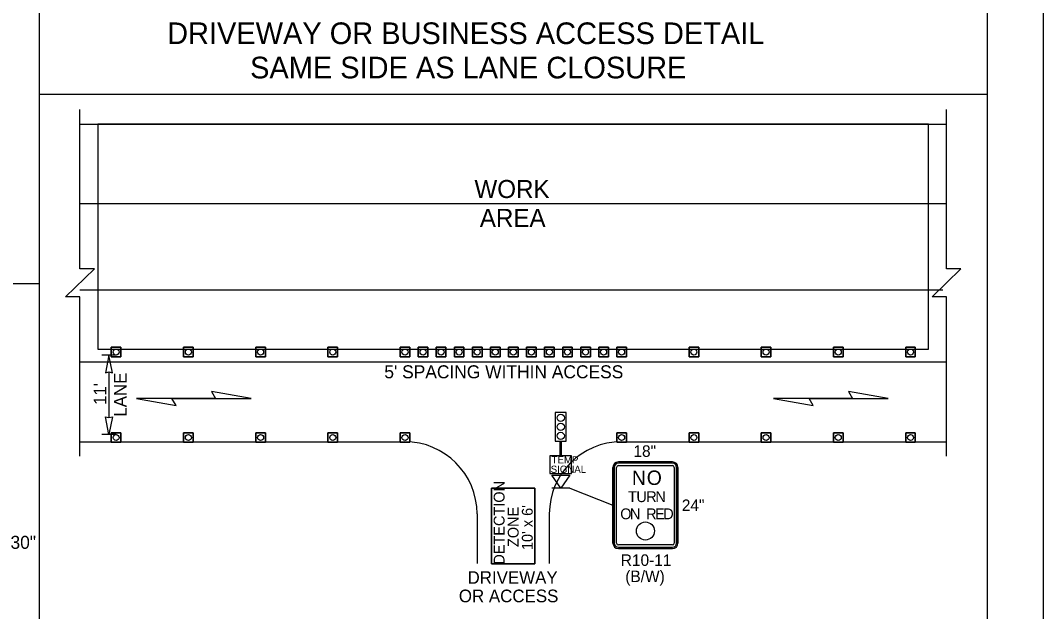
# Model space of a CAD drawing. Extents: x 99979.8 to 100075.7, y 99995 to 100010.7.
# Drawn here: x 100050.4 to 100056.06, y 100004.3 to 100007.58 of the extents above; entities that cross this region are included whole.
import ezdxf

# ---------------------------------------------------------------- set-up
doc = ezdxf.new("R2010")
doc.units = 0
for name, color, linetype in [('Default', 7, 'Continuous'), ('RD_ED_DrivewayEdge', 7, 'Continuous'), ('RD_ED_ShoulderPavedEdge', 7, 'Continuous'), ('RD_MK_LineEdgeWhite', 7, 'Continuous'), ('RD_MK_LineSkipCenter', 7, 'Continuous'), ('SH_DE_DetailHeading2Text', 7, 'Continuous'), ('SH_GI_PlotLimits', 7, 'Continuous'), ('SH_GI_SheetBorder', 7, 'Continuous'), ('TR_SN_ConstructionSigns', 7, 'Continuous'), ('TR_WZ_PortableSignMountBlk-Wht', 7, 'Continuous'), ('TR_WZ_TempSignal', 7, 'Continuous'), ('TR_WZ_TrafficCone', 7, 'Continuous'), ('TR_WZ_WorkAreaLabel', 7, 'Continuous'), ('TR_WZ_WorkZoneDetails', 7, 'Continuous'), ('TR_WZ_WorkZoneTextCurrent', 7, 'Continuous')]:
    doc.layers.add(name, color=color, linetype=linetype)

msp = doc.modelspace()

# ---------------------------------------------------------------- linework, layer by layer
at = {"layer": 'Default'}
msp.add_circle((100053.8574, 100004.7505), 0.05, dxfattribs=at)
at = {"layer": 'RD_ED_DrivewayEdge'}
for p, q in [((100052.925, 100004.845), (100052.925, 100004.5696)), ((100053.325, 100004.845), (100053.325, 100004.5696))]:
    msp.add_line(p, q, dxfattribs=at)
for centre, start, end in [((100052.525, 100004.845), 0, 90), ((100053.725, 100004.845), 90, 180)]:
    msp.add_arc(centre, 0.4, start, end, dxfattribs=at)
at = {"layer": 'RD_ED_ShoulderPavedEdge'}
for p, q in [((100050.725, 100007.005), (100055.525, 100007.005)), ((100050.725, 100005.245), (100052.525, 100005.245)), ((100050.725, 100005.245), (100052.525, 100005.245)), ((100053.725, 100005.245), (100055.525, 100005.245)), ((100053.725, 100005.245), (100055.525, 100005.245))]:
    msp.add_line(p, q, dxfattribs=at)
at = {"layer": 'RD_MK_LineEdgeWhite'}
for p, q in [((100050.725, 100006.565), (100055.525, 100006.565)), ((100055.525, 100005.685), (100050.725, 100005.685))]:
    msp.add_line(p, q, dxfattribs=at)
at = {"layer": 'RD_MK_LineSkipCenter'}
msp.add_lwpolyline([(100055.5043, 100006.085), (100050.725, 100006.085)], dxfattribs=at)
at = {"layer": 'SH_GI_PlotLimits'}
msp.add_lwpolyline([(100039.0625, 99999.6875), (100056.0625, 99999.6875), (100056.0625, 100010.6875), (100039.0625, 100010.6875)], close=True, dxfattribs=at)
at = {"layer": 'SH_GI_SheetBorder'}
msp.add_line((100055.75, 100010.375), (100055.75, 100000), dxfattribs=at)
at = {"layer": 'TR_SN_ConstructionSigns'}
for p, q in [((100053.7074, 100005.133), (100054.0074, 100005.133)), ((100054.0074, 100005.133), (100053.7074, 100005.133)), ((100054.0074, 100005.133), (100053.7074, 100005.133)), ((100054.0074, 100005.1255), (100053.7074, 100005.1255)), ((100053.6774, 100004.683), (100053.6774, 100005.103)), ((100053.6774, 100005.103), (100053.6774, 100004.683)), ((100053.6774, 100005.103), (100053.6774, 100004.683)), ((100053.6849, 100005.103), (100053.6849, 100004.683)), ((100053.6974, 100004.683), (100053.6974, 100005.103)), ((100053.7074, 100005.113), (100054.0074, 100005.113)), ((100054.0174, 100005.103), (100054.0174, 100004.683)), ((100054.0299, 100004.683), (100054.0299, 100005.103)), ((100054.0374, 100005.103), (100054.0374, 100004.683)), ((100054.0374, 100004.683), (100054.0374, 100005.103)), ((100054.0374, 100004.683), (100054.0374, 100005.103)), ((100054.0074, 100004.673), (100053.7074, 100004.673)), ((100053.7074, 100004.6605), (100054.0074, 100004.6605)), ((100054.0074, 100004.653), (100053.7074, 100004.653)), ((100053.7074, 100004.653), (100054.0074, 100004.653)), ((100053.7074, 100004.653), (100054.0074, 100004.653))]:
    msp.add_line(p, q, dxfattribs=at)
for centre, radius, start, end in [((100053.7074, 100005.103), 0.03, 90, 180), ((100053.7074, 100005.103), 0.03, 90, 180), ((100053.7074, 100005.103), 0.03, 90, 180), ((100053.7074, 100005.103), 0.0225, 90, 180), ((100054.0074, 100005.103), 0.03, 0, 90), ((100054.0074, 100005.103), 0.03, 0, 90), ((100054.0074, 100005.103), 0.03, 0, 90), ((100054.0074, 100005.103), 0.0225, 0, 90), ((100053.7074, 100005.103), 0.01, 90, 180), ((100054.0074, 100005.103), 0.01, 0, 90), ((100053.7074, 100004.683), 0.03, 180, 270), ((100053.7074, 100004.683), 0.03, 180, 270), ((100053.7074, 100004.683), 0.03, 180, 270), ((100053.7074, 100004.683), 0.0225, 180, 270), ((100053.7074, 100004.683), 0.01, 180, 270), ((100054.0074, 100004.683), 0.03, 270, 0), ((100054.0074, 100004.683), 0.03, 270, 0), ((100054.0074, 100004.683), 0.0225, 270, 0), ((100054.0074, 100004.683), 0.01, 270, 0), ((100054.0074, 100004.683), 0.03, 270, 0)]:
    msp.add_arc(centre, radius, start, end, dxfattribs=at)
at = {"layer": 'TR_WZ_PortableSignMountBlk-Wht'}
msp.add_line((100053.4383, 100004.9878), (100053.3383, 100004.9878), dxfattribs=at)
msp.add_lwpolyline([(100053.3884, 100004.9878), (100053.3383, 100005.0596), (100053.4383, 100005.0596)], close=True, dxfattribs=at)
at = {"layer": 'TR_WZ_TempSignal'}
for p, q in [((100053.4182, 100005.4071), (100053.3583, 100005.4071)), ((100053.3583, 100005.4071), (100053.3583, 100005.2474)), ((100053.4182, 100005.2474), (100053.4182, 100005.4071)), ((100053.3583, 100005.2474), (100053.4182, 100005.2474)), ((100053.4483, 100005.1674), (100053.3283, 100005.1674)), ((100053.3283, 100005.1674), (100053.3283, 100005.1229)), ((100053.3283, 100005.1229), (100053.3283, 100005.1141)), ((100053.4483, 100005.0696), (100053.4483, 100005.1674)), ((100053.3283, 100005.1141), (100053.3283, 100005.0696)), ((100053.3283, 100005.0696), (100053.4483, 100005.0696))]:
    msp.add_line(p, q, dxfattribs=at)
for points in [[(100053.4182, 100005.4071), (100053.3583, 100005.4071), (100053.3583, 100005.2474), (100053.4182, 100005.2474), (100053.4182, 100005.4071)], [(100053.4483, 100005.1674), (100053.3283, 100005.1674), (100053.3283, 100005.0696), (100053.4483, 100005.0696), (100053.4483, 100005.1674)]]:
    msp.add_lwpolyline(points, dxfattribs=at)
msp.add_lwpolyline([(100053.3858, 100005.2474), (100053.3908, 100005.2474), (100053.3908, 100005.1674), (100053.3858, 100005.1674)], close=True, dxfattribs=at)
for centre in [(100053.3883, 100005.3772), (100053.3883, 100005.3772), (100053.3883, 100005.3273), (100053.3883, 100005.3273), (100053.3883, 100005.2773), (100053.3883, 100005.2773)]:
    msp.add_circle(centre, 0.02, dxfattribs=at)
at = {"layer": 'TR_WZ_TrafficCone'}
for points in [[(100050.899, 100005.7683), (100050.9523, 100005.7683), (100050.9523, 100005.715), (100050.899, 100005.715), (100050.899, 100005.7683)], [(100050.899, 100005.715), (100050.9523, 100005.715), (100050.9523, 100005.7683), (100050.899, 100005.7683), (100050.899, 100005.715)], [(100051.299, 100005.7683), (100051.3523, 100005.7683), (100051.3523, 100005.715), (100051.299, 100005.715), (100051.299, 100005.7683)], [(100051.299, 100005.715), (100051.3523, 100005.715), (100051.3523, 100005.7683), (100051.299, 100005.7683), (100051.299, 100005.715)], [(100051.699, 100005.7683), (100051.7523, 100005.7683), (100051.7523, 100005.715), (100051.699, 100005.715), (100051.699, 100005.7683)], [(100051.699, 100005.715), (100051.7523, 100005.715), (100051.7523, 100005.7683), (100051.699, 100005.7683), (100051.699, 100005.715)], [(100052.099, 100005.7683), (100052.1523, 100005.7683), (100052.1523, 100005.715), (100052.099, 100005.715), (100052.099, 100005.7683)], [(100052.099, 100005.715), (100052.1523, 100005.715), (100052.1523, 100005.7683), (100052.099, 100005.7683), (100052.099, 100005.715)], [(100052.499, 100005.7683), (100052.5523, 100005.7683), (100052.5523, 100005.715), (100052.499, 100005.715), (100052.499, 100005.7683)], [(100052.499, 100005.715), (100052.5523, 100005.715), (100052.5523, 100005.7683), (100052.499, 100005.7683), (100052.499, 100005.715)], [(100052.599, 100005.7683), (100052.6523, 100005.7683), (100052.6523, 100005.715), (100052.599, 100005.715), (100052.599, 100005.7683)], [(100052.599, 100005.715), (100052.6523, 100005.715), (100052.6523, 100005.7683), (100052.599, 100005.7683), (100052.599, 100005.715)], [(100052.699, 100005.7683), (100052.7523, 100005.7683), (100052.7523, 100005.715), (100052.699, 100005.715), (100052.699, 100005.7683)], [(100052.699, 100005.715), (100052.7523, 100005.715), (100052.7523, 100005.7683), (100052.699, 100005.7683), (100052.699, 100005.715)], [(100052.799, 100005.7683), (100052.8523, 100005.7683), (100052.8523, 100005.715), (100052.799, 100005.715), (100052.799, 100005.7683)], [(100052.799, 100005.715), (100052.8523, 100005.715), (100052.8523, 100005.7683), (100052.799, 100005.7683), (100052.799, 100005.715)], [(100052.899, 100005.7683), (100052.9523, 100005.7683), (100052.9523, 100005.715), (100052.899, 100005.715), (100052.899, 100005.7683)], [(100052.899, 100005.715), (100052.9523, 100005.715), (100052.9523, 100005.7683), (100052.899, 100005.7683), (100052.899, 100005.715)], [(100052.999, 100005.7683), (100053.0523, 100005.7683), (100053.0523, 100005.715), (100052.999, 100005.715), (100052.999, 100005.7683)], [(100052.999, 100005.715), (100053.0523, 100005.715), (100053.0523, 100005.7683), (100052.999, 100005.7683), (100052.999, 100005.715)], [(100053.099, 100005.7683), (100053.1523, 100005.7683), (100053.1523, 100005.715), (100053.099, 100005.715), (100053.099, 100005.7683)], [(100053.099, 100005.715), (100053.1523, 100005.715), (100053.1523, 100005.7683), (100053.099, 100005.7683), (100053.099, 100005.715)], [(100053.199, 100005.7683), (100053.2523, 100005.7683), (100053.2523, 100005.715), (100053.199, 100005.715), (100053.199, 100005.7683)], [(100053.199, 100005.715), (100053.2523, 100005.715), (100053.2523, 100005.7683), (100053.199, 100005.7683), (100053.199, 100005.715)], [(100053.299, 100005.7683), (100053.3523, 100005.7683), (100053.3523, 100005.715), (100053.299, 100005.715), (100053.299, 100005.7683)], [(100053.299, 100005.715), (100053.3523, 100005.715), (100053.3523, 100005.7683), (100053.299, 100005.7683), (100053.299, 100005.715)], [(100053.399, 100005.7683), (100053.4523, 100005.7683), (100053.4523, 100005.715), (100053.399, 100005.715), (100053.399, 100005.7683)], [(100053.399, 100005.715), (100053.4523, 100005.715), (100053.4523, 100005.7683), (100053.399, 100005.7683), (100053.399, 100005.715)], [(100053.499, 100005.7683), (100053.5523, 100005.7683), (100053.5523, 100005.715), (100053.499, 100005.715), (100053.499, 100005.7683)], [(100053.499, 100005.715), (100053.5523, 100005.715), (100053.5523, 100005.7683), (100053.499, 100005.7683), (100053.499, 100005.715)], [(100053.599, 100005.7683), (100053.6523, 100005.7683), (100053.6523, 100005.715), (100053.599, 100005.715), (100053.599, 100005.7683)], [(100053.599, 100005.715), (100053.6523, 100005.715), (100053.6523, 100005.7683), (100053.599, 100005.7683), (100053.599, 100005.715)], [(100053.699, 100005.7683), (100053.7523, 100005.7683), (100053.7523, 100005.715), (100053.699, 100005.715), (100053.699, 100005.7683)], [(100053.699, 100005.715), (100053.7523, 100005.715), (100053.7523, 100005.7683), (100053.699, 100005.7683), (100053.699, 100005.715)], [(100054.099, 100005.7683), (100054.1523, 100005.7683), (100054.1523, 100005.715), (100054.099, 100005.715), (100054.099, 100005.7683)], [(100054.099, 100005.715), (100054.1523, 100005.715), (100054.1523, 100005.7683), (100054.099, 100005.7683), (100054.099, 100005.715)], [(100054.499, 100005.7683), (100054.5523, 100005.7683), (100054.5523, 100005.715), (100054.499, 100005.715), (100054.499, 100005.7683)], [(100054.499, 100005.715), (100054.5523, 100005.715), (100054.5523, 100005.7683), (100054.499, 100005.7683), (100054.499, 100005.715)], [(100054.899, 100005.7683), (100054.9523, 100005.7683), (100054.9523, 100005.715), (100054.899, 100005.715), (100054.899, 100005.7683)], [(100054.899, 100005.715), (100054.9523, 100005.715), (100054.9523, 100005.7683), (100054.899, 100005.7683), (100054.899, 100005.715)], [(100055.299, 100005.7683), (100055.3523, 100005.7683), (100055.3523, 100005.715), (100055.299, 100005.715), (100055.299, 100005.7683)], [(100055.299, 100005.715), (100055.3523, 100005.715), (100055.3523, 100005.7683), (100055.299, 100005.7683), (100055.299, 100005.715)], [(100050.899, 100005.295), (100050.9524, 100005.295), (100050.9524, 100005.2417), (100050.899, 100005.2417), (100050.899, 100005.295)], [(100050.899, 100005.2417), (100050.9524, 100005.2417), (100050.9524, 100005.295), (100050.899, 100005.295), (100050.899, 100005.2417)], [(100051.299, 100005.295), (100051.3524, 100005.295), (100051.3524, 100005.2417), (100051.299, 100005.2417), (100051.299, 100005.295)], [(100051.299, 100005.2417), (100051.3524, 100005.2417), (100051.3524, 100005.295), (100051.299, 100005.295), (100051.299, 100005.2417)], [(100051.699, 100005.295), (100051.7523, 100005.295), (100051.7523, 100005.2417), (100051.699, 100005.2417), (100051.699, 100005.295)], [(100051.699, 100005.2417), (100051.7523, 100005.2417), (100051.7523, 100005.295), (100051.699, 100005.295), (100051.699, 100005.2417)], [(100052.099, 100005.295), (100052.1523, 100005.295), (100052.1523, 100005.2417), (100052.099, 100005.2417), (100052.099, 100005.295)], [(100052.099, 100005.2417), (100052.1523, 100005.2417), (100052.1523, 100005.295), (100052.099, 100005.295), (100052.099, 100005.2417)], [(100052.499, 100005.295), (100052.5523, 100005.295), (100052.5523, 100005.2417), (100052.499, 100005.2417), (100052.499, 100005.295)], [(100052.499, 100005.2417), (100052.5523, 100005.2417), (100052.5523, 100005.295), (100052.499, 100005.295), (100052.499, 100005.2417)], [(100053.699, 100005.295), (100053.7523, 100005.295), (100053.7523, 100005.2417), (100053.699, 100005.2417), (100053.699, 100005.295)], [(100053.699, 100005.2417), (100053.7523, 100005.2417), (100053.7523, 100005.295), (100053.699, 100005.295), (100053.699, 100005.2417)], [(100054.099, 100005.295), (100054.1523, 100005.295), (100054.1523, 100005.2417), (100054.099, 100005.2417), (100054.099, 100005.295)], [(100054.099, 100005.2417), (100054.1523, 100005.2417), (100054.1523, 100005.295), (100054.099, 100005.295), (100054.099, 100005.2417)], [(100054.499, 100005.295), (100054.5523, 100005.295), (100054.5523, 100005.2417), (100054.499, 100005.2417), (100054.499, 100005.295)], [(100054.499, 100005.2417), (100054.5523, 100005.2417), (100054.5523, 100005.295), (100054.499, 100005.295), (100054.499, 100005.2417)], [(100054.899, 100005.295), (100054.9523, 100005.295), (100054.9523, 100005.2417), (100054.899, 100005.2417), (100054.899, 100005.295)], [(100054.899, 100005.2417), (100054.9523, 100005.2417), (100054.9523, 100005.295), (100054.899, 100005.295), (100054.899, 100005.2417)], [(100055.299, 100005.295), (100055.3523, 100005.295), (100055.3523, 100005.2417), (100055.299, 100005.2417), (100055.299, 100005.295)], [(100055.299, 100005.2417), (100055.3523, 100005.2417), (100055.3523, 100005.295), (100055.299, 100005.295), (100055.299, 100005.2417)]]:
    msp.add_lwpolyline(points, dxfattribs=at)
for centre in [(100050.9257, 100005.7417), (100051.3257, 100005.7417), (100051.7257, 100005.7417), (100052.1257, 100005.7417), (100052.5257, 100005.7417), (100052.6257, 100005.7417), (100052.7257, 100005.7417), (100052.8257, 100005.7417), (100052.9257, 100005.7417), (100053.0257, 100005.7417), (100053.1257, 100005.7417), (100053.2257, 100005.7417), (100053.3257, 100005.7417), (100053.4257, 100005.7417), (100053.5257, 100005.7417), (100053.6257, 100005.7417), (100053.7257, 100005.7417), (100054.1257, 100005.7417), (100054.5257, 100005.7417), (100054.9257, 100005.7417), (100055.3257, 100005.7417), (100050.9257, 100005.2683), (100051.3257, 100005.2683), (100051.7257, 100005.2683), (100052.1257, 100005.2683), (100052.5257, 100005.2683), (100053.7257, 100005.2683), (100054.1257, 100005.2683), (100054.5257, 100005.2683), (100054.9257, 100005.2683), (100055.3257, 100005.2683)]:
    msp.add_circle(centre, 0.0167, dxfattribs=at)
at = {"layer": 'TR_WZ_WorkZoneDetails'}
for p, q in [((100050.5, 100010.275), (100050.5, 100001.2259)), ((100055.75, 100007.1677), (100050.5, 100007.1677)), ((100050.5, 100006.1205), (100045.25, 100006.1205)), ((100050.9257, 100005.725), (100050.8457, 100005.725)), ((100050.8857, 100005.6313), (100050.8857, 100005.3787)), ((100051.4761, 100005.485), (100051.235, 100005.485)), ((100051.235, 100005.485), (100051.4761, 100005.485)), ((100055.0052, 100005.485), (100054.7641, 100005.485)), ((100054.7641, 100005.485), (100055.0052, 100005.485)), ((100050.9257, 100005.285), (100050.8457, 100005.285)), ((100053.4383, 100004.9878), (100053.6774, 100004.893))]:
    msp.add_line(p, q, dxfattribs=at)
for points in [[(100050.725, 100005.165), (100050.725, 100006.0476), (100050.645, 100006.0476), (100050.805, 100006.2024), (100050.725, 100006.2024), (100050.725, 100007.085)], [(100055.525, 100005.165), (100055.525, 100006.0476), (100055.445, 100006.0476), (100055.605, 100006.2024), (100055.525, 100006.2024), (100055.525, 100007.085)], [(100053.005, 100004.5678), (100053.005, 100004.9878), (100053.245, 100004.9878), (100053.245, 100004.5678), (100053.005, 100004.5678)], [(100053.245, 100004.5678), (100053.245, 100004.9878), (100053.005, 100004.9878), (100053.005, 100004.5678), (100053.245, 100004.5678)]]:
    msp.add_lwpolyline(points, dxfattribs=at)
for points in [[(100050.825, 100007.005), (100050.825, 100005.7583), (100055.425, 100005.7583), (100055.425, 100007.005)], [(100050.8857, 100005.725), (100050.8664, 100005.6267), (100050.8857, 100005.6313), (100050.905, 100005.6267)], [(100051.6727, 100005.485), (100051.4539, 100005.5236), (100051.4761, 100005.485)], [(100055.2017, 100005.485), (100054.9829, 100005.5236), (100055.0052, 100005.485)], [(100051.0385, 100005.485), (100051.2573, 100005.4464), (100051.235, 100005.485)], [(100054.5675, 100005.485), (100054.7864, 100005.4464), (100054.7641, 100005.485)], [(100050.8857, 100005.285), (100050.8664, 100005.3833), (100050.8857, 100005.3787), (100050.905, 100005.3833)]]:
    msp.add_lwpolyline(points, close=True, dxfattribs=at)

# ---------------------------------------------------------------- texts
at = {"layer": 'Default'}
for s, height, p in [('N', 0.08, (100053.7826, 100005.0055)), ('O', 0.08, (100053.865, 100005.0055)), ('T', 0.06, (100053.7613, 100004.9105)), ('U', 0.06, (100053.8072, 100004.9105)), ('R', 0.06, (100053.862, 100004.9105)), ('N', 0.06, (100053.9127, 100004.9105)), ('O', 0.06, (100053.718, 100004.8155)), ('N', 0.06, (100053.7714, 100004.8155)), ('R', 0.06, (100053.8613, 100004.8155)), ('E', 0.06, (100053.9105, 100004.8155)), ('D', 0.06, (100053.956, 100004.8155))]:
    msp.add_text(s, height=height, dxfattribs=at).set_placement(p)
at = {"layer": 'SH_DE_DetailHeading2Text'}
for s, p in [('DRIVEWAY OR BUSINESS ACCESS DETAIL', (100051.2082, 100007.4477)), ('SAME SIDE AS LANE CLOSURE', (100051.6677, 100007.2577))]:
    msp.add_text(s, height=0.12, rotation=360, dxfattribs=at).set_placement(p)
at = {"layer": 'TR_SN_ConstructionSigns'}
for s, height, p in [('18"', 0.064, (100053.7909, 100005.161)), ('24"', 0.064, (100054.0589, 100004.861)), ('30"', 0.072, (100050.3406, 100004.6517)), ('R10-11', 0.064, (100053.7209, 100004.557)), ('(B/W)', 0.064, (100053.7458, 100004.4674))]:
    msp.add_text(s, height=height, rotation=360, dxfattribs=at).set_placement(p)
at = {"layer": 'TR_WZ_TempSignal'}
for s, p in [('TEMP', (100053.3377, 100005.1245)), ('SIGNAL', (100053.3327, 100005.0725))]:
    msp.add_text(s, height=0.04, dxfattribs=at).set_placement(p)
at = {"layer": 'TR_WZ_WorkAreaLabel'}
for s, p in [('WORK', (100052.9105, 100006.595)), ('AREA', (100052.9401, 100006.435))]:
    msp.add_text(s, height=0.1, rotation=360, dxfattribs=at).set_placement(p)
at = {"layer": 'TR_WZ_WorkZoneDetails'}
for s, p in [('DETECTION', (100053.077, 100004.564)), ("10' x 6'", (100053.233, 100004.6448)), ('ZONE', (100053.155, 100004.6615))]:
    msp.add_text(s, height=0.06, rotation=90, dxfattribs=at).set_placement(p)
at = {"layer": 'TR_WZ_WorkZoneTextCurrent'}
for s, height, p in [("5' SPACING WITHIN ACCESS", 0.072, (100052.4111, 100005.5963)), ('DRIVEWAY', 0.07, (100052.8721, 100004.4578)), ('OR ACCESS', 0.07, (100052.8239, 100004.3558))]:
    msp.add_text(s, height=height, dxfattribs=at).set_placement(p)
for s, p in [('LANE', (100050.9837, 100005.3835)), ("11'", (100050.8717, 100005.4482))]:
    msp.add_text(s, height=0.07, rotation=90, dxfattribs=at).set_placement(p)

doc.saveas('drawing.dxf')
